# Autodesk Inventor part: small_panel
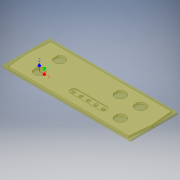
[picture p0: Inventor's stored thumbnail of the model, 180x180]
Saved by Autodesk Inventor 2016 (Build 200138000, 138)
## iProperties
Created: 2016-12
Part Number: small_panel
Material: Типовые
Document SubType Name: Modeling
Designer: admin
Density: 1 g/cm^3
Appearance: По умолчанию
Author: admin
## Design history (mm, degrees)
sketch "Эскиз1"
  geometry: L1 (-89, -31.5)-(89, -31.5); L2 (89, 31.5)-(-89, 31.5); L3 (-89, 31.5)-(-92, 0); L4 (-92, 0)-(-89, -31.5); L5 (89, 31.5)-(92, 0); L6 (92, 0)-(89, -31.5); 3 further points
  constraints: 12 end point, 2 parallel, 1 coincident, 1 horizontal, 1 midpoint, 1 vertical alignment
extrude "Выдавливание1" new body sketch "Эскиз1" distance "d2" = 3; taper "d3" = 0 deg
sketch "Эскиз2"
  geometry: L1 (-66.55, 18.952)-(-66.55, 11.048); L2 (-66.55, -18.952)-(-66.55, -11.048); L3 (22.7, 12.252)-(22.7, 17.748); L4 (37.3, 12.252)-(37.3, 17.748); L5 (52.7, 12.252)-(52.7, 17.748); L6 (67.3, 12.252)-(67.3, 17.748); L7 (52.7, -12.252)-(52.7, -17.748); L8 (67.3, -12.252)-(67.3, -17.748); C1 r 11 at (60, -15); C2 r 11 at (60, 15); C3 r 11.5 at (-60, -15); C4 r 11.5 at (-60, 15); C5 r 11 at (30, 15); C6 r 11.5 at (-60, -15); A1 r 7.8 centre (30, 15) between (22.7, 12.252) and (37.3, 12.252); A2 r 7.8 centre (30, 15) between (37.3, 17.748) and (22.7, 17.748); A3 r 7.65 centre (-60, 15) between (-66.55, 11.048) and (-66.55, 18.952); A4 r 7.65 centre (-60, -15) between (-66.55, -18.952) and (-66.55, -11.048); A5 r 7.8 centre (60, 15) between (52.7, 12.252) and (67.3, 12.252); A6 r 7.8 centre (60, 15) between (67.3, 17.748) and (52.7, 17.748); A7 r 7.8 centre (60, -15) between (52.7, -17.748) and (67.3, -17.748); A8 r 7.8 centre (60, -15) between (67.3, -12.252) and (52.7, -12.252); 5 further points
  constraints: 16 end point, 16 point on circle, 14 centre point, 5 coincident, 2 vertical
extrude "Выдавливание2" cut sketch "Эскиз2" distance "d39" = 10; taper "d40" = 0 deg
sketch "Эскиз3" dims "d61" = 10
  geometry: L1 (-60, -15)-(60, -15); C1 r 2.55 at (35, -15); C2 r 2.55 at (24, -15); C3 r 2.55 at (13, -15); C4 r 2.55 at (2, -15); C5 r 2.55 at (-9, -15); A1 r 7.65 centre (-60, -15) between (-66.55, -18.952) and (-66.55, -11.048) reference; A2 r 7.8 centre (60, -15) between (52.7, -17.748) and (67.3, -17.748) reference; 1 further point
  constraints: 5 centre point, 2 end point, 2 horizontal, 1 point on line, 8 other
  dimensions: "d54" = 5.1 diameter of C1; "d55" = 25 distance of C1.centre L1.end; "d58" = 11 distance of C1.centre C2.centre
extrude "Выдавливание3" cut sketch "Эскиз3" distance "d63" = 10; taper "d64" = 0 deg
sketch "Эскиз4"
  geometry: L1 (-9, -10)-(35, -10); L2 (-9, -20)-(35, -20); C1 r 2.55 at (-9, -15) reference; C2 r 2.55 at (35, -15) reference; A1 r 5 centre (-9, -15) between (-9, -10) and (-9, -20); A2 r 5 centre (35, -15) between (35, -20) and (35, -10); 1 further point
  constraints: 4 end point, 4 point on circle, 2 centre point, 2 coincident, 2 tangent
extrude "Выдавливание4" cut sketch "Эскиз4" distance "d67" = 1.2; taper "d68" = 0 deg
node "Твердое тело1"
other parameters: "d7" = 15.6
